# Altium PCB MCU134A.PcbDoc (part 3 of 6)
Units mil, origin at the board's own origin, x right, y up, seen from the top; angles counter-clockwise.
Board outline 4163.98 x 2693.8 mil, 6 copper layers (Top Layer, GND1, SIG1, PWR, GND2, Bottom), stack 58.132 mil thick; 218 components, 287 nets, 1260 pads, 770 vias.
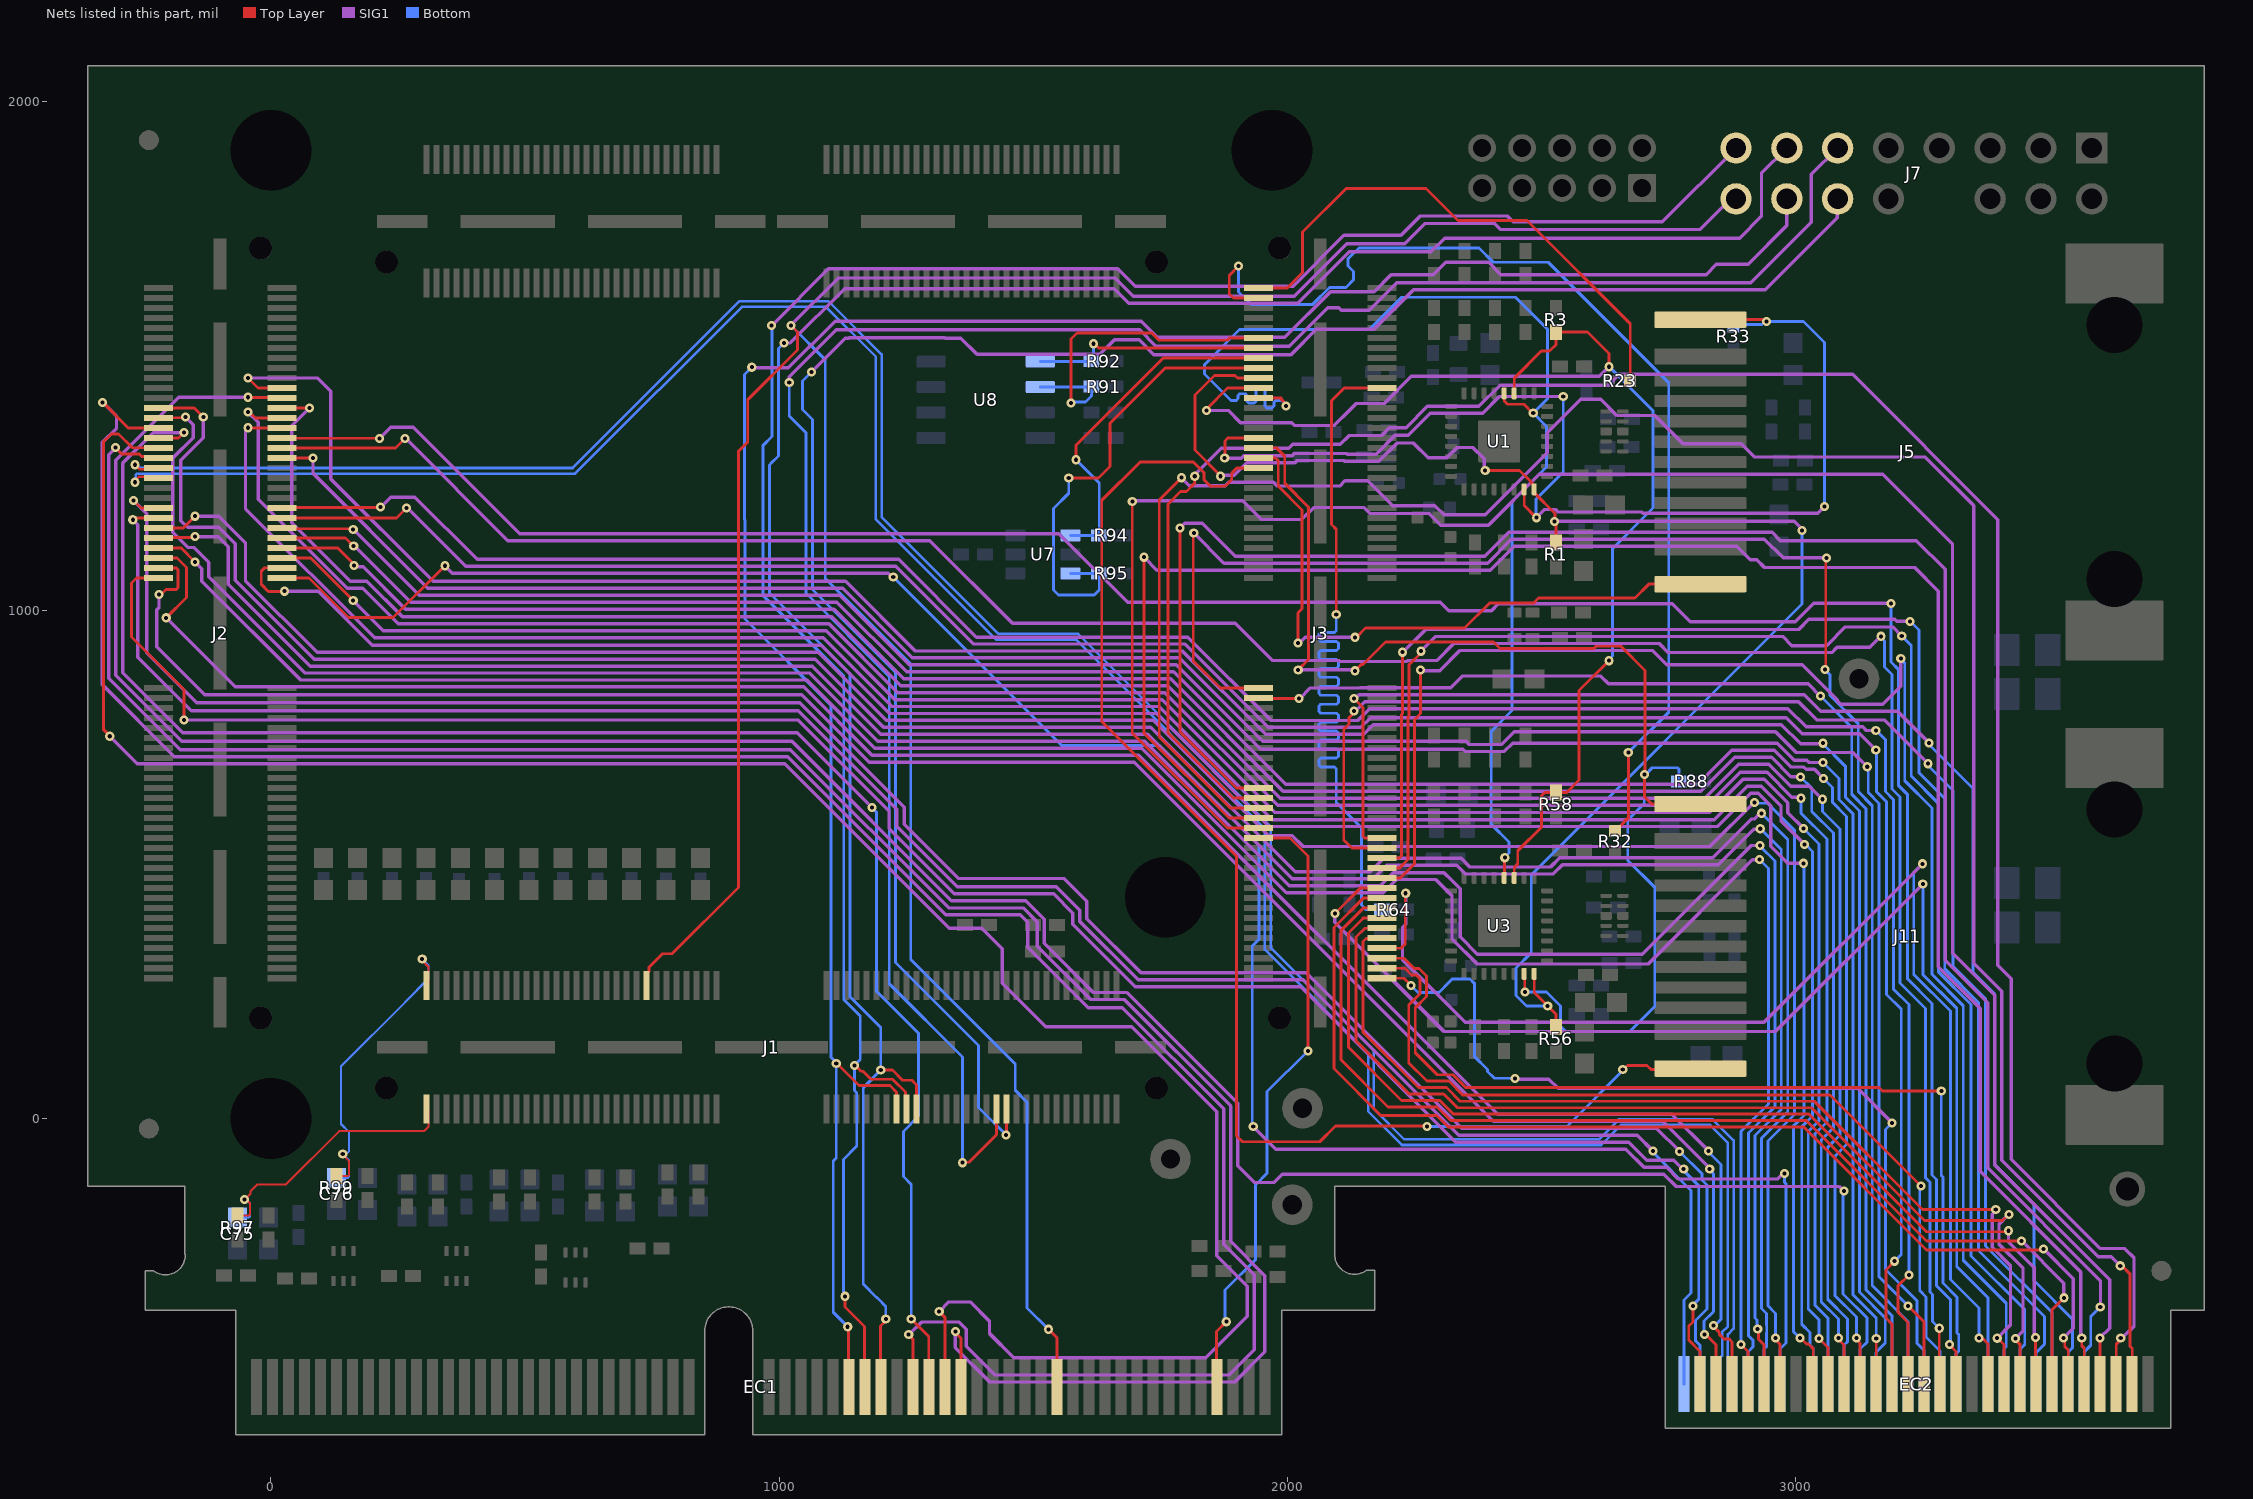
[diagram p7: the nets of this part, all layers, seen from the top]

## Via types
v1: diameter 18, hole 8, Top Layer to Bottom, tented both sides, 761 vias
v2: diameter 19.68, hole 7.87, Top Layer to Bottom, tented both sides, 9 vias

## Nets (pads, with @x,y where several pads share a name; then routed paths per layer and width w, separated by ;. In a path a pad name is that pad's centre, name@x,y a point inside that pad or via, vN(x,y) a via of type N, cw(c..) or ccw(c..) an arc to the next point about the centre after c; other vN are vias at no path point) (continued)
CON1_PIN119: C75.1 J1.119 R97.2 | length 587.5
  Top Layer w4: R97.2@-66.15,-191.38 -43.48,-191.38 -41.14,-189.03 -41.14,-167.11 -48.54,-159.71 v1(-51.64,-159.71) -39.69,-147.77 -39.69,-142.79 -26.91,-130 29.44,-130 134.44,-25 301.25,-25 310.21,-16.04 310.21,-10.38 309.87,-10.04 309.87,14.5 J1.119@305.87,18.5
  Bottom w4: C75.1@-66.15,-195.32 -43.48,-195.31 -41.14,-192.97 -41.14,-170.43 -41.14,-167.11 -48.54,-159.71 v1(-51.64,-159.71)
CON1_PIN120: C76.1 J1.120 R99.2 | length 683.8
  Top Layer w4: R99.2@128.85,-113.07 151.58,-113.07 153.93,-110.73 153.93,-84 141.43,-71.5 v1(141.43,-70) ; v1(297.71,314) 297.71,310.5 310.21,298 310.21,290.38 309.87,290.04 309.87,265.5 J1.120@305.87,261.5
  Bottom w4: C76.1@128.85,-117.01 151.58,-117.01 153.93,-114.66 153.93,-82.5 v1(141.43,-70) 144.1,-67.32 151.2,-67.32 153.93,-64.6 153.93,-26.92 138,-11 138,102.96 264,228.96 264,229.07 310.21,275.28 310.21,301.5 v1(297.71,314)
CON2_PIN21: EC2.146 J2.21 | length 4908.8
  Top Layer w5.66: v1(-45,1457) -25.28,1437.28 J2.21@21.5,1437.28
  SIG1 w6.66: v1(-45,1457) 91.38,1457 117.83,1430.55 117.83,1258.17 319.28,1056.72 1130.72,1056.72 1267.72,919.72 1793.12,919.72 1957.18,755.66 2150.2,755.66 2169.2,774.66 2972.34,774.66 3010,737 3052.67,737 v1(3054,738.33)
  Bottom w5.66: v1(3054,738.33) 3054,737 3098.02,692.98 3098.02,632.5 3125.68,604.84 3125.68,-341.78 3176.66,-392.76 3176.66,-442.19 3158.58,-460.27 EC2.146@3158.58,-522.97
CON2_PIN23: EC2.144 J2.23 | length 5141.8
  Top Layer w5.66: v1(-45,1419) -44.3,1418.3 20.8,1418.3 J2.23@21.5,1417.6
  SIG1 w6.66: v1(-45,1419) -181.25,1419 -304.99,1295.26 -304.99,871.63 -175.36,742 1025.36,742 1339.15,428.22 1485.56,428.22 1521.66,392.11 1521.66,344.66 1618.66,247.66 1684.62,247.66 1902.16,30.11 1902.16,-93.16 1935,-126 1974.22,-126 1990.4,-109.81 2740.81,-109.81 2765,-134 3085.66,-134 3094.66,-143 v1(3095.19,-143)
  Bottom w5.66: v1(3095.19,-143) 3093.66,-144.53 3093.66,-345.56 3141,-392.9 3141,-440.05 3127.09,-453.96 EC2.144@3127.09,-522.97
CON2_PIN25: EC2.142 J2.25 | length 4782.2
  Top Layer w5.66: J2.25@21.5,1397.91 76.05,1397.91 v1(76.25,1398.11)
  SIG1 w6.66: v1(76.25,1398.11) 40.78,1362.64 40.78,1172.22 156,1057 189,1057 258.98,987.02 1103.83,987.02 1239.43,851.42 1764.83,851.42 1985.91,630.34 2821.34,630.34 2888,697 2947.32,697 2990.65,653.67 3027.33,653.67 v1(3053,628)
  Bottom w5.66: v1(3053,628) 3053,604 3087.32,569.68 3087.32,-32.68 3063.32,-56.68 3063.32,-355.78 3102,-394.46 3102,-414 3102.17,-414.17 3102.17,-439.39 3095.59,-445.96 EC2.142@3095.59,-522.97
CON2_PIN26: EC2.132 J2.26 | length 4990.8
  Top Layer w5.66: J2.26@-221.5,1397.91 -150.91,1397.91 v1(-133,1380)
  SIG1 w6.66: v1(-133,1380) -133,1339 -177,1295 -177,1176.08 -163.92,1163 -102.68,1163 -70.22,1130.53 -70.22,1059.22 85.36,903.64 1071.3,903.64 1205.48,769.46 1730.88,769.46 2015.31,485.03 2163.03,485.03 2190,512 2342,512 2359.33,494.67 2517.87,494.67 2536.2,513 2836.7,513 2912.75,589.05 2918.55,589.05 2929.84,600.34 v1(2932.91,600.34)
  Bottom w5.66: v1(2932.91,600.34) 2933.02,600.34 2984.66,548.7 2984.66,12.54 2933.04,-39.08 2933.04,-373.94 2942.75,-383.65 2942.75,-406.05 2943.38,-406.68 2943.38,-421.45 2942.75,-422.08 2942.75,-449.32 2938.11,-453.96 EC2.132@2938.11,-522.97
CON2_PIN27: EC2.140 J2.27 | length 4779.5
  Top Layer w5.66: v1(-45,1390) -42.04,1390 -30.27,1378.23 J2.27@21.5,1378.23
  SIG1 w6.66: v1(-45,1390) -25,1370 -25,1218.68 150.34,1043.34 180.66,1043.34 250.64,973.36 1098.17,973.36 1233.77,837.76 1759.17,837.76 1980.93,616 2826.32,616 2891.32,681 2944,681 2992.83,632.17 3008.83,632.17 v1(3011,630)
  Bottom w5.66: v1(3011,630) 3011,600.63 3062,549.63 3062,-6.9 3038,-30.9 3038,-367 3064.09,-393.09 EC2.140@3064.09,-522.97
CON2_PIN28: EC2.130 J2.28 | length 5053.6
  Top Layer w5.66: J2.28@-221.5,1378.23 -221.03,1378.7 -168.42,1378.7 v1@-167.95,1379.17
  SIG1 w6.66: v1(-167.95,1380) -152.74,1364.8 -152.74,1339.7 -192.95,1299.49 -192.95,1153.03 -163.4,1123.48 -151.55,1123.48 -122,1093.92 -122,1066 67.68,876.32 1059.98,876.32 1194.16,742.14 1719.57,742.14 2003.99,457.71 2183.03,457.71 2208.98,483.66 2308.34,483.66 2324.17,467.83 2340,452 2340,357 2374,323 2698.68,323 2912.68,537 v1(2930,537)
  Bottom w5.66: EC2.130@2906.61,-522.97 2906.61,-459.36 2916,-449.98 2916,-436 2907.72,-427.72 2907.72,-28.59 2959.34,23.03 2959.34,506.25 2930,535.59 v1(2930,537)
CON2_PIN29: EC2.138 J2.29 | length 4729.9
  Top Layer w5.66: v1(-45,1359) -44.77,1358.77 21.27,1358.77 J2.29@21.5,1358.54
  SIG1 w6.66: v1(-45,1359) -45,1355.93 -50,1350.93 -50,1200 203.96,946.04 1086.85,946.04 1222.45,810.44 1747.86,810.44 1970.3,588 2840,588 2905.34,653.34 2933.02,653.34 2971.34,615.02 2971.34,585.66 v1(3018,539)
  Bottom w5.66: v1(3018,539) 3020,539 3033.7,525.3 3033.7,5.04 3012.16,-16.5 3012.16,-405.16 3028.43,-421.43 3028.43,-446.43 3035,-453 3035,-520.57 EC2.138@3032.6,-522.97
CON2_PIN30: EC1.75 J2.30 | length 4669.5
  Top Layer w5.66: v1(-331,1409) -280.54,1358.54 J2.30@-221.5,1358.54 ; v1(1255,-425) 1255,-426.24 1263.25,-434.49 EC1.75@1263.25,-528.32
  SIG1 w6.66: v1(-331,1409) -303.67,1381.67 -303.67,1358.41 -332.31,1329.77 -332.31,854.31 -190,712 1016.73,712 1328.28,400.45 1474.69,400.45 1489,386.14 1489,337 1608,218 1675.64,218 1874.77,18.87 1874.77,-247.66 1935,-307.89 1935,-455 1885,-505 1425,-505 1368.33,-448.33 1368.33,-414.59 1354.41,-400.67 1280.25,-400.67 1255.92,-425 v1(1255,-425)
CON2_PIN31: EC2.155 J2.31 | length 4961
  Top Layer w5.66: J2.31@21.5,1338.86 21.93,1338.43 213.57,1338.43 v1(214,1338) ; v1(3303.33,-445.1) 3303.33,-446.06 3316,-458.73 EC2.155@3316,-532
  SIG1 w6.66: v1(214,1338) 236,1360 280,1360 489.36,1150.64 1550.68,1150.64 1685.98,1015.34 2300.66,1015.34 2317.32,998.68 2401.83,998.68 2415.49,1012.34 2757.67,1012.34 2793,977.01 2999.13,977.01 3035.44,1013.33 v1(3188,1013.33)
  Bottom w5.66: v1(3188,1013.33) 3188,898 3202.32,883.68 3202.32,655.68 3220,638 3220,275 3268.66,226.34 3268.66,-111.62 3277.35,-120.32 3277.35,-329.26 3305.32,-357.22 3305.32,-384.39 3305,-384.71 3305,-443.43 v1(3303.33,-445.1)
CON2_PIN32: EC1.77 J2.32 | length 3407
  Top Layer w5.66: J2.32@-221.5,1338.86 -181.68,1338.86 v1(-171.07,1349.47) ; v1(1260,-395) 1294.39,-429.39 EC1.77@1294.39,-527.97
  SIG1 w6.66: v1(-171.07,1349.47) -231.46,1349.47 -291.33,1289.6 -291.33,877.28 -173.05,759 1035.47,759 v1(1182.94,611.53)
  Bottom w5.66: v1(1182.94,611.53) 1191.34,603.13 1191.34,250.66 1274.49,167.51 1274.49,4.49 1244.51,-25.49 1244.51,-114.51 1260,-130 v1(1260,-395)
CON2_PIN33: EC2.153 J2.33 | length 4891.3
  Top Layer w5.66: J2.33@21.5,1319.17 245.17,1319.17 v1(264,1338) ; v1(3282.89,-412.89) 3282.89,-521.3 EC2.153@3284.57,-522.97
  SIG1 w6.66: v1(264,1338) 265,1338 466.02,1136.98 1296.66,1136.98 1459.28,974.36 1897.64,974.36 1971.02,900.98 2101.85,900.98 2103.77,899.06 2234.59,899.06 2236.51,900.98 2293.98,900.98 2327.44,934.44 2731.69,934.44 2749.44,916.68 3071.34,916.68 3081.66,927 3146.33,927 v1(3168,948.67)
  Bottom w5.66: v1(3168,948.67) 3168,946.18 3175,939.18 3175,888 3189.66,873.34 3189.66,648.28 3205.66,632.28 3205.66,266.34 3256,216 3256,-116.87 3264.69,-125.56 3264.69,-341.29 3269.66,-346.26 3269.66,-399.66 v1(3282.89,-412.89)
CON2_PIN34: EC1.79 J2.34 | length 4521.6
  Top Layer w5.66: v1(-317,752) -317,752.73 -329,764.73 -329,1331.87 -313.87,1347 -299.68,1347 -272.35,1319.67 -221.99,1319.67 J2.34@-221.5,1319.17 ; v1(1315,-380) 1326.1,-391.1 EC1.79@1326.1,-528.18
  SIG1 w6.66: v1(-317,752) -263,698 1011.41,698 1334.88,374.53 1398.72,374.53 1439,334.26 1439,266 1525,180 1694.32,180 1861.11,13.21 1861.11,-270.19 1921.05,-330.12 1921.05,-389.02 1839.17,-470.89 1461.62,-470.89 1413.99,-423.26 1413.99,-398.82 1376.34,-361.17 1333.83,-361.17 v1(1315,-380)
CON2_PIN35: EC2.151 J2.35 | length 4671.8
  Top Layer w5.66: J2.35@21.5,1299.49 v1(82.91,1299.49) v1@83,1299.57 ; v1(3221.58,-369) 3222,-369 3253.07,-400.07 EC2.151@3253.07,-522.97
  SIG1 w6.66: v1(82.91,1299.49) 82.91,1269.09 308.94,1043.06 1125.06,1043.06 1262.06,906.06 1787.46,906.06 1951.52,742 2351.95,742 2358.28,735.67 2421.43,735.67 2446.76,761 2960.59,761 3001.59,720 3113,720 3141,692 v1(3141.17,692)
  Bottom w5.66: v1(3141.17,692) 3143,690.17 3143,641.23 3164.51,619.72 3164.51,-311.51 3221.58,-368.58 v1(3221.58,-369)
CON2_PIN36: EC1.81 J2.36 | length 4454.7
  Top Layer w5.66: v1(-306,1320.17) -292.84,1307.01 -258.79,1307.01 -254.44,1302.66 -224.67,1302.66 J2.36@-221.5,1299.49 ; v1(1346.82,-419) 1346.82,-421.65 1357.66,-432.5 EC1.81@1357.66,-528.25
  SIG1 w6.66: v1(-306,1320.17) -306,1318.61 -318.65,1305.96 -318.65,865.97 -178.34,725.66 1022.39,725.66 1333.94,414.11 1480.35,414.11 1508,386.46 1508,339 1613,234 1678.96,234 1888.43,24.53 1888.43,-242 1955.65,-309.22 1955.65,-459.35 1896.34,-518.66 1414.6,-518.66 1346.82,-450.88 v1(1346.82,-419)
CON2_PIN38: EC2.128 J2.38 | length 4932.2
  Top Layer w5: v1@-266,1286.18 -266,1285.49 -257.54,1277.03 -224.27,1277.03 J2.38@-221.5,1279.8
  Bottom w5: v1(-267.03,1286.18) -263.98,1286.18 -257.6,1279.8 593.86,1279.8 922.28,1608.22 1096.78,1608.22 1201.63,1503.37 1201.63,1183.37 1431.78,953.22 1588.65,953.22 1967.27,574.6 1967.27,336.6 2170.29,133.58 2170.29,18.71 2230.07,-41.07 2613.07,-41.07 2652.35,-1.78 2836.65,-1.78 2878.22,-43.35 2878.22,-413.78 2867,-425 2867,-514.85 EC2.128@2875.12,-522.97
CON2_PIN40: EC2.126 J2.40 | length 4930.3
  Top Layer w5: v1(-267.03,1251.75) -267.03,1254.83 -258.97,1262.89 -224.27,1262.89 J2.40@-221.5,1260.12
  Bottom w5: v1(-267.03,1251.75) v1@-264.97,1253.81 ; v1@-267.03,1255.03 -266.06,1256 -266.06,1265.65 -263.13,1268.58 598.51,1268.58 926.92,1597 1092.13,1597 1190.41,1498.72 1190.41,1178.72 1427.13,942 1584,942 1956.05,569.95 1956.05,331.95 2159.07,128.93 2159.07,14.07 2225.42,-52.29 2617.71,-52.29 2657,-13 2832,-13 2867,-48 2867,-409.13 2855.78,-420.35 2855.78,-466.83 2852.85,-469.76 2852.54,-469.76 2843.62,-478.68 EC2.126@2843.62,-522.97
CON2_PIN45: EC2.149 J2.45 | length 4685.4
  Top Layer w5.66: J2.45@21.5,1201.06 22.46,1202.03 215.03,1202.03 v1(216,1203) ; EC2.149@3221.58,-522.97 3221.58,-401.58 3202,-382 3202,-329 v1(3223,-308)
  SIG1 w6.66: v1(216,1203) 235.59,1222.59 283.41,1222.59 405.68,1100.32 1235.08,1100.32 1388.36,947.04 1804.44,947.04 1968.5,782.98 2138.89,782.98 2162.23,806.32 2984.79,806.32 3020.79,770.32 3132,770.32 3139.01,763.31 3157.69,763.31 v1(3158,763)
  Bottom w5.66: v1(3158,763) 3159,763 3176.83,745.17 3176.83,643.21 3193,627.04 3193,254 3223,224 v1(3223,-308)
CON2_PIN46: EC2.124 J2.46 | length 4320.8
  Top Layer w5.66: v1(-270.24,1215.57) -255.73,1201.06 J2.46@-221.5,1201.06
  SIG1 w6.66: v1(-270.24,1215.57) -244.36,1189.69 -244.36,916.36 -146,818 1041.03,818 1246.57,612.46 1246.57,578.75 1353.32,472 1561,472 1605.34,427.66 1605.34,393.1 1712.12,286.32 2037.36,286.32 2343.02,-19.34 2726.34,-19.34 v1(2772,-65)
  Bottom w5.66: v1(2772,-65) 2816,-109 2816,-121.1 2825.66,-130.76 2825.66,-375.05 2803.17,-397.54 2803.17,-437.4 2812.13,-446.36 EC2.124@2812.13,-522.97
CON2_PIN47: EC2.147 J2.47 | length 4643.9
  Top Layer w5.66: J2.47@21.5,1181.38 247.38,1181.38 v1(267,1201) ; EC2.147@3190.08,-522.97 3190.08,-405.08 3178,-393 3178,-298 v1(3195,-281)
  SIG1 w6.66: v1(267,1201) 269,1201 383.34,1086.66 1229.42,1086.66 1382.7,933.38 1798.78,933.38 1962.84,769.32 2144.54,769.32 2163.88,788.66 2981.34,788.66 3013.34,756.66 3126.34,756.66 v1(3158,725)
  Bottom w5.66: v1(3158,725) 3159,724 3159,643.14 3179,623.14 3179,244 3207.95,215.05 3207.95,-268.05 v1(3195,-281)
CON2_PIN48: EC2.122 J2.48 | length 4238.5
  Top Layer w5.66: v1(-271.67,1178) -268.33,1178 -264.95,1181.38 J2.48@-221.5,1181.38
  SIG1 w6.66: v1(-271.67,1178) -262,1168.33 -262,907.73 -156.27,802 1037.71,802 1231.34,608.37 1231.34,574.66 1350.46,455.54 1545.78,455.54 1591.68,409.64 1591.68,387.44 1706.46,272.66 2031.7,272.66 2337.36,-33 2688.45,-33 v1(2719.61,-64.16)
  Bottom w5.66: v1(2719.61,-64.16) 2719.61,-66.7 2794.65,-141.74 2794.65,-343.39 2780.63,-357.4 EC2.122@2780.63,-522.97
CON2_PIN49: EC2.145 J2.49 | length 4503.8
  Top Layer w5.66: J2.49@21.5,1161.69 22.84,1160.35 160.65,1160.35 v1(162,1159) ; EC2.145@3158.58,-522.97 3158.83,-522.72 v1(3158.83,-433)
  SIG1 w6.66: v1(162,1159) 291.62,1029.4 1119.4,1029.4 1256.4,892.4 1781.81,892.4 1947.88,726.33 2345.67,726.33 2349.99,722.01 2427.09,722.01 2443.21,738.14 2964.14,738.14 2997.26,705.01 3022.23,705.01 3026.9,700.34 v1(3054,700.34)
  Bottom w5.66: v1(3054,700.34) 3085.36,668.98 3085.36,627.26 3113.02,599.6 3113.02,-347.02 3158.83,-392.83 v1(3158.83,-433)
CON2_PIN50: EC2.133 J2.50 | length 4721.8
  Top Layer w5.66: J2.50@-221.5,1161.69 -172.31,1161.69 v1(-149,1185) ; v1(2960.58,-432) 2960.58,-435.34 2969.61,-444.37 EC2.133@2969.61,-522.97
  SIG1 w6.66: v1(-149,1185) -102.21,1185 -50,1132.79 -50,1058.32 91.02,917.3 1076.96,917.3 1211.14,783.12 1736.54,783.12 1963.49,556.17 2009.83,556.17 2031,535 2831.59,535 2917.94,621.35 v1(2919.36,621.35)
  Bottom w5.66: v1(2919.36,621.35) 2920.57,620.13 2944.87,620.13 2998,567 2998,7.98 2945.7,-44.32 2945.7,-368.7 2960.58,-383.58 v1(2960.58,-432)
CON2_PIN51: EC2.143 J2.51 | length 4525.7
  Top Layer w5.66: J2.51@21.5,1142.01 146.99,1142.01 v1(163,1126) ; v1(3120,-432) 3120,-435.34 3127.09,-442.43 EC2.143@3127.09,-522.97
  SIG1 w6.66: v1(163,1126) 165,1126 275.26,1015.74 1113.74,1015.74 1250.74,878.74 1776.15,878.74 1997.23,657.66 2807.66,657.66 2874.48,724.48 2958.48,724.48 2991.6,691.35 3016.57,691.35 3021.24,686.68 3037.32,686.68 v1(3055,669)
  Bottom w5.66: v1(3055,669) 3072.7,651.3 3072.7,622.01 3100.36,594.35 3100.36,-51.64 3077.36,-74.64 3077.36,-348.36 3120,-391 v1(3120,-432)
CON2_PIN52: EC2.131 J2.52 | length 4669
  Top Layer w5.66: J2.52@-221.5,1142.01 -220.17,1143.34 -150.33,1143.34 v1(-149,1144.67) ; v1(2925.55,-414.07) 2927.12,-415.63 2927.12,-434.39 2938.11,-445.38 EC2.131@2938.11,-522.97
  SIG1 w6.66: v1(-149,1144.67) -103.67,1144.67 -83.88,1124.88 -83.88,1050.88 77.02,889.98 1065.64,889.98 1199.82,755.8 1725.22,755.8 2009.65,471.37 2169.37,471.37 2196,498 2333,498 2349.99,481.01 2523.53,481.01 2541.52,499 2848,499 2918.03,569.03 2929.62,569.03 v1(2930.59,570)
  Bottom w5.66: v1(2925.55,-414.07) 2924.51,-413.03 2924.51,-396.58 2920.38,-392.44 2920.38,-33.83 2972,17.79 2972,529 v1@2931,570
CON2_PIN53: EC2.141 J2.53 | length 4482.5
  Top Layer w5.66: J2.53@21.5,1122.32 131.68,1122.32 163.21,1090.79 v1(163.21,1087.71) ; v1(3084.34,-432) 3084.34,-434.68 3095.59,-445.93 EC2.141@3095.59,-522.97
  SIG1 w6.66: v1(163.21,1087.71) 165.38,1085.54 181.46,1085.54 264.92,1002.08 1108.09,1002.08 1245.08,865.08 1770.49,865.08 1991.57,644 2813.32,644 2880.14,710.82 2952.82,710.82 2991.01,672.63 3009.37,672.63 v1(3010,672)
  Bottom w5.66: v1(3010,672) 3032,650 3032,604 3074.66,561.34 3074.66,-18.34 3050.66,-42.34 3050.66,-361.03 3084.34,-394.71 v1(3084.34,-432)
CON2_PIN54: EC2.129 J2.54 | length 4727.9
  Top Layer w5.66: J2.54@-221.5,1122.32 -176.32,1122.32 v1(-149,1095) ; v1(2893,-445) 2906.61,-458.61 EC2.129@2906.61,-522.97
  SIG1 w6.66: v1(-149,1095) -149,1094.82 -135.66,1081.48 -135.66,1056.66 58.34,862.66 1054.32,862.66 1188.5,728.48 1713.91,728.48 1998.34,444.05 2188.69,444.05 2214.64,470 2292.58,470 2324,438.58 2324,353.68 2373.83,303.85 2709.85,303.85 2915.26,509.26 v1(2929,509.26)
  Bottom w5.66: v1(2893,-445) 2893,-25.4 2946.68,28.28 2946.68,491.51 2929,509.19 v1(2929,509.26)
CON2_PIN55: EC2.139 J2.55 | length 4411.1
  Top Layer w5.66: J2.55@21.5,1102.64 78.36,1102.64 v1(162,1019) ; v1(3046.26,-433) 3064.09,-450.83 EC2.139@3064.09,-522.97
  SIG1 w6.66: v1(162,1019) 221.3,959.7 1092.51,959.7 1228.11,824.1 1753.52,824.1 1975.62,602 2831.64,602 2896.64,667 2938.68,667 2985,620.68 2985,601.41 v1(3015.71,570.71)
  Bottom w5.66: v1(3015.71,570.71) 3046.36,540.05 3046.36,-4.64 3025,-26 3025,-375 3046.26,-396.26 v1(3046.26,-433)
CON2_PIN56: EC2.127 J2.56 | length 4146
  Top Layer w5.66: J2.56@-221.5,1102.64 -184.46,1102.64 -165.91,1084.09 -165.91,1025.09 v1(-206,985) ; v1(2838.68,-407.32) 2838.68,-409.56 2849.92,-420.81 2849.92,-424.74 2859.49,-434.3 2869.45,-434.3 2875.12,-439.97 EC2.127@2875.12,-522.97
  SIG1 w6.66: v1(-206,985) -70,849 1048.67,849 1182.85,714.82 1707.18,714.82 2414.02,7.98 2756.81,7.98 v1(2828.93,-64.16)
  Bottom w5.66: v1(2828.93,-64.16) 2828.93,-65.93 2853.45,-90.45 2853.45,-395.12 2841.25,-407.32 v1(2838.68,-407.32)
CON2_PIN57: EC2.137 J2.57 | length 4487.3
  Top Layer w5: EC2.137@3032.6,-522.97 EC2.137@3032.6,-520.57
  Top Layer w5.66: J2.57@23.69,1083.48 23.63,1083.42 -12.22,1083.42 -19,1076.64 -19,1051 -5,1037 26.28,1037 v1(26.65,1037.36) ; v1(3008.64,-432.36) 3010.13,-432.36 3021.76,-443.98 3025.76,-443.98 3035,-453.22 EC2.137@3035,-520.57
  SIG1 w6.66: v1(26.65,1037.36) 93.32,1037.36 199.72,930.96 1082.61,930.96 1216.79,796.78 1742.2,796.78 1964.64,574.34 2846.42,574.34 2911.76,639.68 2926.95,639.68 2951.24,615.39 2951.24,535.76 2985,502 v1(3015.87,502)
  Bottom w5.66: v1(3008.64,-432.36) 2996.36,-420.08 2996.36,-14.39 3016.53,5.78 3016.53,501.34 v1(3015.87,502)
CON2_PIN58: EC2.125 J2.58 | length 4149.2
  Top Layer w5.66: J2.58@-221.5,1082.95 -186.27,1082.95 -182.95,1079.64 -182.95,1044.32 -186.27,1041 -206.66,1041 -216.78,1030.88 v1(-220.12,1030.88) ; v1(2821,-425) 2823.24,-425 2843.53,-445.28 2843.53,-522.87 EC2.125@2843.62,-522.97
  SIG1 w6.66: v1(-220.12,1030.88) -220.12,1004.71 -224.33,1000.5 -224.33,928.33 -130,834 1044.35,834 1177.19,701.16 1698.84,701.16 2405.68,-5.68 2738.6,-5.68 2831.14,-98.22 v1(2831.14,-99.58)
  Bottom w5.66: v1(2821,-425) 2820.17,-424.17 2820.17,-398.44 2838.32,-380.29 2838.32,-109.07 2831.14,-101.89 v1(2831.14,-99.58)
CON2_PIN59: EC2.134 J2.59 | length 4298.9
  Top Layer w5.66: J2.59@21.5,1063.27 74.97,1063.27 152.79,985.45 240.45,985.45 v1(342.5,1087.5)
  SIG1 w6.66: v1(342.5,1087.5) 357,1073 1215.01,1073 1222.43,1065.58 v1(1224.58,1065.58) ; v1(1933,-16) 1977.32,-60.32 2666,-60.32 2701.83,-96.15 2746.47,-96.15 2769.65,-119.33 2964.39,-119.33 2975.46,-108.26 v1(2978.53,-108.26)
  Bottom w5.66: v1(1224.58,1065.58) 1556.16,734 1748,734 1944.5,537.5 1944.5,352.5 1931,339 1931,-14 v1(1933,-16) ; EC2.134@2969.61,-522.97 2969.61,-453.96 2981.36,-442.21 2981.36,-128.58 2978.53,-125.75 v1(2978.53,-108.26)
CON2_PIN60: EC2.123 J2.60 | length 4171.3
  Top Layer w5.66: J2.60@-221.5,1063.27 -264.35,1063.27 -274.02,1053.6 -274.02,947.02 -171,844 v1(-171,784) ; v1(2798.46,-369) 2798,-369.46 2798,-400.79 2790.02,-408.77 2790.02,-436.29 2812.13,-458.39 EC2.123@2812.13,-522.97
  SIG1 w6.66: v1(-171,784) 1036.39,784 1216.34,604.06 1216.34,570.34 1344.8,441.88 1540.12,441.88 1578.02,403.98 1578.02,381.78 1700.8,259 2026.05,259 2331.71,-46.66 2671.66,-46.66 2707.49,-82.49 2760.61,-82.49 2777.79,-99.67 v1(2779.97,-99.67)
  Bottom w5.66: v1(2779.97,-99.67) 2779.97,-102.97 2809.49,-132.49 2809.49,-355.76 2798.46,-366.79 v1(2798.46,-369)
CON3_PIN2: EC2.152 J3.2 | length 1780.6
  Top Layer w5.66: J3.2@2186.5,275.87 2229.38,275.87 v1(2243.51,261.74)
  SIG1 w6.66: v1(2448,78.83) 2449.43,77.4 2514.39,77.4 2532.79,59 3122.12,59 v1(3190.12,-9)
  Bottom w5.66: v1(2243.51,261.74) 2257.25,248 2298.22,248 2317,266.78 2317,267 2324.55,274.55 2359.45,274.55 2368,266 2368,122.37 2394.17,96.2 2394.17,92.61 2407.82,78.97 v1@2447.86,78.97 ; v1(3190.12,-9) 3177.17,-21.95 3177.17,-297.17 3239.41,-359.41 3239.41,-442.65 3253.07,-456.31 EC2.152@3253.07,-522.97
CON3_PIN4: EC2.154 J3.4 | length 1774.2
  Top Layer w5.66: J3.4@2186.5,295.55 2231.33,295.55 2244.54,282.34 2253.66,282.34 2261.34,274.66 2261.34,245.34 2239,223 2239,109 2274.66,73.34 2318.2,73.34 2345.2,46.34 3067.58,46.34 v1(3246.86,-132.95)
  Bottom w5.66: v1(3246.86,-132.95) 3244.5,-135.31 3244.5,-142.27 3244.34,-142.43 3244.34,-338.85 3257,-351.51 3257,-429.99 3284.57,-457.55 EC2.154@3284.57,-522.97
CON3_PIN6: EC2.156 J3.6 | length 1930.7
  Top Layer w5.66: J3.6@2186.5,315.24 2229.55,315.24 2249.79,295 2258.91,295 2274,279.9 2274,240.1 2251.66,217.76 2251.66,129.34 2295,86 2326.08,86 2351.08,61 3164.06,61 3171.06,54 v1(3286.83,54)
  Bottom w5.66: v1(3286.83,54) 3286.83,-111.89 3290.01,-115.07 3290.01,-324.01 3317.98,-351.98 3317.98,-421.98 3321.13,-425.13 3321.13,-444.06 ; EC2.156@3316,-532 3316,-462.99 3321.16,-457.83 3321.16,-444.09
CON3_PIN8: EC2.159 J3.8 | length 2581.5
  Top Layer w5.66: J3.8@2186.5,334.92 2223.92,334.92 2232,343 2232,442 v1(2233,443) ; v1(3361.15,-432) 3363.51,-434.36 3369.49,-434.36 3379.06,-443.92 EC2.159@3379.06,-522.97
  SIG1 w6.66: v1(2233,443) 2233,381.83 2226.67,375.5 2226.67,312.41 2350.08,189 2938,189 v1(3250,501)
  Bottom w5.66: v1(3250,501) 3232.66,483.66 3232.66,283.34 3304.66,211.34 3304.66,-316.85 3361.15,-373.34 v1(3361.15,-432)
CON3_PIN10: EC2.161 J3.10 | length 1986.1
  Top Layer w5.66: J3.10@2186.5,354.61 2185.89,354 2155,354 2149.12,348.12 2149.12,169.5 2257.94,60.68 2312.96,60.68 2339.96,33.68 3036.88,33.68 3249.56,-179 v1(3394,-179) ; v1(3396.81,-432.45) 3397.62,-432.45 3410,-444.83 EC2.161@3410,-522.42
  SIG1 w6.66: v1(3394,-179) 3394,-181.31 3386.73,-188.57 3386.73,-253.3 3423,-289.56 3423,-406.26 v1(3396.81,-432.45)
CON3_PIN12: EC2.163 J3.12 | length 2070.3
  Top Layer w5.66: J3.12@2186.5,374.29 2152.72,374.29 2135.34,356.91 2135.34,152.66 2239.98,48.02 2307.72,48.02 2334.72,21.02 3031.64,21.02 3253.66,-201 3407.27,-201 3419.27,-189 v1(3420,-189) ; v1(3433,-433) 3433,-436.34 3442.05,-445.39 EC2.163@3442.05,-522.97
  SIG1 w6.66: v1(3420,-189) 3400.39,-208.61 3400.39,-247.64 3447.73,-294.98 3447.73,-418.27 v1(3433,-433)
CON3_PIN14: EC2.165 J3.14 | length 2077.9
  Top Layer w5.66: J3.14@2186.5,393.98 2149.46,393.98 2145.86,390.37 2120.11,364.62 2120.11,139.89 2224.64,35.36 2300.02,35.36 2327.02,8.36 3026.4,8.36 3257.76,-223 3417,-223 v1(3419,-221) ; v1(3472.1,-431.01) 3472.1,-521.53 EC2.165@3473.54,-522.97
  SIG1 w6.66: v1(3419,-221) 3419,-242.82 3469.96,-293.78 3469.96,-428.86 v1(3472.1,-431.01)
CON3_PIN16: EC2.167 J3.16 | length 2166
  Top Layer w5.66: J3.16@2186.5,413.66 2149.46,413.66 2106,370.2 2106,115 2198.3,22.7 2294.78,22.7 2321.78,-4.3 3021.15,-4.3 3257.85,-241 v1(3445,-241) ; EC2.167@3505.04,-522.97 3505.04,-375.96 v1(3528,-353)
  SIG1 w6.66: v1(3445,-241) 3528,-324 v1(3528,-353)
CON3_PIN18: EC2.169 J3.18 | length 2242.4
  Top Layer w5.66: J3.18@2186.5,433.35 2149.46,433.35 2092,375.88 2092,98 2184,6 2293.58,6 2316.78,-17.2 3016.15,-17.2 3257.78,-258.83 3486.17,-258.83 v1(3488,-257) ; v1(3527.51,-432) 3529.87,-434.36 3529.87,-448.87 3536.54,-455.54 EC2.169@3536.54,-522.97
  SIG1 w6.66: v1(3488,-257) 3546.33,-315.33 3546.33,-413.18 v1(3527.51,-432)
CON3_PIN20: EC2.160 J3.20 | length 2534.1
  Top Layer w5.66: v1(2093.6,403) 2143.63,453.03 J3.20@2186.5,453.03
  SIG1 w6.66: v1(2093.6,403) 2093.6,385.73 2308.32,171 2960.49,171 v1(3250.49,461)
  Bottom w5.66: v1(3250.49,461) 3250.49,283.41 3317.32,216.58 3317.32,-291.32 3378.98,-352.98 3378.98,-439.83 3379.06,-439.91 EC2.160@3379.06,-522.97
CON3_PIN22: EC2.162 J3.22 | length 3055.1
  Top Layer w5.66: J3.22@2186.5,472.72 2221.81,472.72 2250.2,501.1 2250.2,784.43 2262.27,796.51 v1(2262.27,882.65)
  SIG1 w6.66: v1(2262.27,882.65) 2264.19,880.73 2299.73,880.73 2339.78,920.78 2718.24,920.78 2746.39,892.62 3013.3,892.62 3081.9,824.02 3081.9,822 3089.23,814.67 3171.76,814.67 3207.17,850.08 v1(3207.17,905)
  Bottom w5.66: v1(3207.17,905) 3207.17,903.32 3214.98,895.51 3214.98,664.24 3268.32,610.9 3268.32,283.49 3330,221.81 3330,-279 3414.64,-363.64 3414.64,-448.77 3410,-453.41 3410,-522.42 EC2.162@3410.55,-522.97
CON3_PIN24: EC2.164 J3.24 | length 3042.5
  Top Layer w5.66: J3.24@2186.5,492.4 2220.4,492.4 2237.54,509.54 2237.54,789.68 2239.54,791.68 2239.54,892.54 2263,916 v1(2263,919.31)
  SIG1 w6.66: v1(2263,919.31) 2292.03,948.34 2974.66,948.34 2992.66,930.34 3061.02,930.34 3097.68,967 3191,967 v1(3209,949)
  Bottom w5.66: v1(3209,949) 3227.64,930.36 3227.64,673.58 3280.98,620.24 3280.98,288.73 3345.44,224.27 3345.44,-270.44 3451,-376 3451,-445.01 3442.05,-453.96 EC2.164@3442.05,-522.97
CON3_PIN26: EC2.166 J3.26 | length 3086.3
  Top Layer w5.66: J3.26@2186.5,512.09 2186.62,512.21 2220.21,512.21 2224.88,516.88 2224.88,794.92 2226.88,796.92 2226.88,917.27 v1(2227,917.39)
  SIG1 w6.66: v1(2227,917.39) 2227.39,917.39 2272,962 3006,962 3026,982 3195.32,982 3199.32,978 v1(3225,978)
  Bottom w5.66: v1(3225,978) 3226.01,978 3243,961.01 3243,679.98 3293.64,629.34 3293.64,294.51 3359.84,228.32 3359.84,-259.84 3489.93,-389.93 3489.93,-444.24 3473.54,-460.63 EC2.166@3473.54,-522.97
CON3_PIN28: EC2.168 J3.28 | length 2853.9
  Top Layer w5.66: v1(2131.29,801.31) 2131.29,797.97 2121.59,788.27 2121.59,776.3 2111,765.71 2111,548 2127.23,531.77 J3.28@2186.5,531.77
  SIG1 w6.66: v1(2131.29,801.31) 2133.61,801.31 2152.28,819.98 3005.91,819.98 3041.89,784 3174.83,784 v1(3260.83,698)
  Bottom w5.66: v1(3260.83,698) 3260.83,694.68 3310,645.51 3310,300 3374,236 3374,-251 3505.04,-382.04 EC2.168@3505.04,-522.97
CON3_PIN29: EC1.113 J3.29 | length 1233.4
  Top Layer w5.66: EC1.113@1860.86,-529.14 1860.86,-419.14 v1(1880,-400) ; J3.29@1943.5,551.46 2005.14,551.46 2040.42,516.18 v1(2040.42,132.95)
  Bottom w5.66: v1(1880,-400) 1877.64,-397.64 1877.64,-390.77 1877.38,-390.51 1877.38,-337.83 1937.17,-278.05 1937.17,-130.84 1960.17,-107.84 1960.17,52.7 v1(2040.42,132.95)
CON3_PIN30: EC2.170 J3.30 | length 2874.8
  Top Layer w5.66: v1(2130.95,826.31) 2131.51,826.31 2149.12,808.7 2149.12,554.77 2152.44,551.46 J3.30@2186.5,551.46
  SIG1 w6.66: v1(2130.95,826.31) 2134.02,826.31 2141.05,833.34 2146.45,833.34 2146.75,833.64 3017.36,833.64 3049.99,801.01 3200.66,801.01 v1(3262.67,739)
  Bottom w5.66: v1(3262.67,739) 3262.67,735.66 3349,649.33 3349,288 3392,245 3392,-91.34 3469,-168.34 3469,-319.22 3545.34,-395.56 3545.34,-450.66 3536.54,-459.46 EC2.170@3536.54,-522.97
CON3_PIN31: EC2.173 J3.31 | length 4322.3
  Top Layer w5.66: v1(1695,1214) 1695,758.52 1882.38,571.14 J3.31@1943.5,571.14 ; v1(3599,-432) 3599,-522.44 EC2.173@3599.53,-522.97
  SIG1 w6.66: v1(1695,1214) 1695.98,1214.98 1912.37,1214.98 1948.82,1178.53 2028.53,1178.53 2052,1202 2151,1202 2162.78,1190.22 2279.15,1190.22 2301.9,1167.47 2395.88,1167.47 2495.58,1267.16 3171.85,1267.16 3309,1130.02 3309,325 3392,242 3392,-91.68 3618,-317.68 3618,-413 v1(3599,-432)
CON3_PIN33: EC2.171 J3.33 | length 3949.7
  Top Layer w5.66: v1(1718,1104.26) 1718,757.83 1885,590.83 J3.33@1943.5,590.83 ; v1(3563.17,-432) 3563.17,-447.46 3568.03,-452.32 EC2.171@3568.03,-522.97
  SIG1 w6.66: v1@1718.26,1104.26 1743.54,1078.98 2399.66,1078.98 2446.68,1125.99 2884.32,1125.99 2911.32,1099 2924,1099 2939,1084 3234.32,1084 3281,1037.32 3281,298.53 3363.23,216.3 3363.23,-103.86 3561.57,-302.2 3561.57,-430.4 v1(3563.17,-432)
CON3_PIN35: EC2.177 J3.35 | length 4464.2
  Top Layer w5.66: v1@1791.6,1260.46 1748.14,1217.01 1748.14,750.26 1887.89,610.51 J3.35@1943.5,610.51 ; v1(3639,-290) 3642.34,-290 3657.83,-305.49 3657.83,-448.09 3662.52,-452.78 EC2.177@3662.52,-522.97
  SIG1 w6.66: v1@1791.65,1260.65 1807.09,1245.2 1877.97,1245.2 1884.41,1251.64 1972.87,1251.64 1980.19,1244.32 2102.99,1244.32 2113.45,1254.78 2158.71,1254.78 2207.85,1205.64 2290.36,1205.64 2308.54,1187.46 2389.46,1187.46 2511.45,1309.45 2511.45,1349.37 2577.41,1415.33 2616.43,1415.33 2648.65,1383.11 2722.82,1383.11 2778.62,1327.31 2893.61,1327.31 2919.59,1301.33 3255.67,1301.33 3351,1206 3351,305.62 3406,250.62 3406,-82 3596,-272 3621,-272 v1(3639,-290)
  other v1: 1791.6,1260.69
CON3_PIN37: EC2.175 J3.37 | length 4404.4
  Top Layer w5.66: v1(1817.93,1263.53) 1817.93,1249.85 1801.52,1233.44 1790.16,1233.44 1765.17,1208.45 1765.17,758.87 1893.85,630.2 J3.37@1943.5,630.2 ; EC2.175@3631.02,-522.97 3631.02,-444.32 3640,-435.34 v1(3640,-432)
  SIG1 w6.66: v1(1817.93,1263.53) 1817.93,1266.23 1870.33,1318.62 2003,1318.62 2010.71,1326.34 2104.34,1326.34 2121.77,1343.77 2185.4,1343.77 2200.63,1359 2233.68,1359 2275.72,1401.04 2377.04,1401.04 2419,1443 2632,1443 2653,1464 3112.32,1464 3398,1178.32 3398,301 3424.44,274.56 3424.44,-80.44 3600.03,-256.03 3647.86,-256.03 3666,-274.17 3666,-409.07 3643.07,-432 v1(3640,-432)
CON3_PIN39: EC2.172 J3.39 | length 3930.4
  Top Layer w5.66: v1(1789,1162) 1789,760.96 1900.08,649.88 J3.39@1943.5,649.88
  SIG1 w6.66: v1(1789,1162) 1789.57,1162 1798.57,1171 1833,1171 1897.7,1106.3 2388.35,1106.3 2435.36,1153.31 2953.93,1153.31 2970.25,1137 3237.92,1137 3294.66,1080.26 3294.66,311.34 3378,228 3378,-97 3600,-319 3600,-370.67 v1(3599.67,-371)
  Bottom w5.66: EC2.172@3568.03,-522.97 3568.03,-459.33 3581,-446.36 3581,-390 3599.67,-371.33 v1(3599.67,-371)
CON3_PIN57: EC2.148 J3.57 | length 2553.1
  Top Layer w5.66: J3.57@1943.5,827.05 1944.03,826.52 2022.48,826.52 v1(2023,826)
  SIG1 w6.66: v1(2023,826) 2024.56,826 2045.56,847 2142.71,847 2143.01,847.3 2321.3,847.3 2344.46,870.46 2616.54,870.46 2632,855 3025,855 v1(3049,831)
  Bottom w5.66: v1(3049,831) 3110.68,769.32 3110.68,637.74 3138.34,610.08 3138.34,-336.53 3190.08,-388.27 EC2.148@3190.08,-522.97
CON3_PIN59: EC2.150 J3.59 | length 3402.2
  Top Layer w5.66: v1(1816,1152) 1815,1151 1815,900 1868.27,846.73 J3.59@1943.5,846.73 ; v1(3058,883) 3059.5,884.5 3059.5,1101.5 v1(3061,1103)
  SIG1 w6.66: v1(1816,1152) 1875.36,1092.64 2394,1092.64 2441.02,1139.65 2938.82,1139.65 2975.47,1103 v1(3061,1103)
  Bottom w5.66: v1(3058,883) 3068,873 3068,832 3123.34,776.66 3123.34,642.99 3151,615.33 3151,-329 3221.58,-399.58 EC2.150@3221.58,-522.97
DAC_SPI_CLK: EC1.71 J1.41 J7.13 | length 4529.4
  Top Layer w5.66: EC1.71@1199.85,-528.73 1199.85,-408.49 1210,-398.34 v1(1210,-395) ; v1(1200,95) 1223.28,95 1243.08,75.2 1261.23,75.2 1270.43,66 J1.41@1270.43,18.5
  SIG1 w6.66: v1(1009.66,1525.83) 1022.3,1525.83 1129.25,1632.78 1659.46,1632.78 1688.24,1604 2020.46,1604 2121.63,1705.18 2282.67,1705.18 2309.7,1732.21 2890.21,1732.21 2933,1775 2933,1859.44 J7.13@2982.94,1909.38
  Bottom w5.66: v1(1009.66,1525.83) 998.66,1514.82 998.66,1303.66 984.31,1289.31 984.31,1288.6 981.33,1285.61 981.33,1033.63 1139.77,875.18 1139.77,239.32 1200,179.1 v1(1200,95) 1165.5,60.5 1165.5,-325.72 1191.95,-352.17 1192.39,-352.17 1202.39,-362.17 1202.39,-362.6 1209.98,-370.2 v1(1210,-395)
DAC_SPI_PICO: EC1.67 J1.45 J7.14 | length 4530.5
  Top Layer w5.66: v1(1112.41,108) 1114,108 1157.49,64.51 1217.96,64.51 1231.06,51.41 J1.45@1231.06,18.5 ; v1(1135,-410) 1136.86,-411.86 EC1.67@1136.86,-528.73
  SIG1 w6.66: v1(946.33,1478.13) 947.7,1476.76 1018.39,1476.76 1110.42,1568.78 1712.63,1568.78 1744.54,1536.87 1995.19,1536.87 2084.98,1626.66 2170.66,1626.66 2204.05,1660.05 2287.33,1660.05 2311.92,1684.64 2395.95,1684.64 2420.28,1660.31 2824.01,1660.31 2844.38,1680.67 2906.67,1680.67 2982.94,1756.94 J7.14@2982.94,1809.38
  Bottom w5.66: v1(946.33,1478.13) 932.17,1463.97 932.17,1178.17 933,1177.34 933,982.63 1101.79,813.84 1101.79,120.53 v1@1114.32,108 ; v1(1112.41,108) 1112.41,-77.81 1106.5,-83.72 1106.5,-381.5 v1(1135,-410)
DAC_SPI_POCI: EC1.69 J1.43 J7.15 | length 4447.9
  Top Layer w5.66: v1(1130,-350) 1130,-371.15 1168.35,-409.51 EC1.69@1168.35,-528.73 ; v1(1148.07,104.45) 1149.54,104.45 1161.17,92.82 1165.18,92.82 1180.83,77.17 1223.2,77.17 1248.69,51.68 1248.69,20.56 J1.43@1250.75,18.5
  SIG1 w6.66: v1(985.13,1560.03) 1097.14,1672.05 1666.39,1672.05 1701.04,1637.39 2011.35,1637.39 2111.52,1737.56 2223.71,1737.56 2261.8,1775.65 2433.14,1775.65 2444.78,1764 2737.56,1764 J7.15@2882.94,1909.38
  Bottom w5.66: v1(985.13,1560.03) 986,1559.17 986,1342 968.67,1324.67 968.67,1028.39 1127.11,869.94 1127.11,234.08 1159.78,201.41 1159.78,116.17 v1(1148.07,104.45) 1148.07,54.8 1152.84,50.03 1152.84,-54.34 1126.47,-80.71 1126.47,-340.51 1127.64,-341.68 1127.64,-347.64 v1(1130,-350)
DAC_SPI_PTE: EC1.93 J1.76 J7.16 | length 5746.3
  Top Layer w5.66: J1.76@738.94,261.5 738.94,284.04 743.79,288.89 743.79,297.41 770.38,324 789.56,324 920,454.44 920,1312.68 938.3,1330.98 938.3,1414.12 1036,1511.81 1036,1547.52 v1(1023.14,1560.38) ; v1(1530,-415) 1546.72,-431.72 EC1.93@1546.72,-528.32
  SIG1 w6.66: v1(1023.14,1560.38) 1116.32,1653.56 1661.48,1653.56 1697.04,1618 2013.35,1618 2116.52,1721.17 2230.88,1721.17 2270.53,1760.83 2408.08,1760.83 2419.91,1749 2812,1749 2872.38,1809.38 J7.16@2882.94,1809.38
  Bottom w5.66: v1(1023.14,1560.38) 1090.88,1492.64 1090.88,1062.49 1258.98,894.4 1258.98,312.74 1464.57,107.15 1464.57,55.43 1488.08,31.92 1488.08,-373.08 v1(1530,-415)
ECAT_PHY0_CLK: J3.117 R32.1 | length 2151.2
  Top Layer w5.66: v1(1904,1677) 1885.83,1658.83 1885.83,1622.45 1893.82,1614.45 J3.117@1943.5,1614.45 ; R32.1@2645,565.67 2653.98,574.65 2671,591.67 v1(2671,719.81)
  Bottom w5.66: v1(1904,1677) 1904,1626.35 1928.47,1601.88 2050.1,1601.88 2083.22,1635 2115.22,1635 2130.34,1650.11 2130.34,1666.55 2119.67,1677.21 2119.67,1691.55 2141.05,1712.92 2377.08,1712.92 2405.36,1684.64 2513.36,1684.64 2750.53,1447.47 2750.53,799.34 v1(2671,719.81)
ECAT_PHY1_CLK: J3.119 R23.1 | length 1081.9
  Top Layer w5.66: J3.119@1943.5,1634.13 2000.06,1634.13 2030.17,1664.25 2030.17,1744.09 2116.01,1829.92 2272.94,1829.92 2336.04,1766.82 2471.6,1766.82 2674.73,1563.69 R23.1@2674.73,1451.12
EEPROM_I2CSCL: J1.23 J7.12 | length 3958.2
  Top Layer w5.66: v1(1446.74,-32.43) 1447.59,-31.58 J1.23@1447.6,18.5
  SIG1 w6.66: v1(1064,1469) 1130.38,1535.38 1137.37,1535.38 1137.71,1535.72 1326.05,1535.72 1326.39,1535.38 1357.35,1535.38 1389.42,1503.31 1631.31,1503.31 1660,1532 1708.39,1532 1737.45,1502.94 2007.29,1502.94 2056.93,1552.59 2170.59,1552.59 2248.34,1630.34 2940.34,1630.34 3082.38,1772.38 3082.38,1808.82 J7.12@3082.94,1809.38
  Bottom w5.66: v1(1064,1469) 1046.17,1451.17 1046.17,1394.83 1065.56,1375.44 1065.56,1040.86 1229.32,877.1 1229.32,306.59 1392.54,143.37 1392.54,21.77 1445.56,-31.25 v1(1446.74,-32.43)
EEPROM_I2CSDA: J1.25 J7.11 | length 4163.2
  Top Layer w5.66: v1(1360.92,-87.14) 1361.69,-86.37 1373.57,-86.37 1427.91,-32.03 J1.25@1427.91,18.5
  SIG1 w6.66: v1(1020.03,1447.73) 1020.03,1459.08 1112.6,1551.65 1709.49,1551.65 1741.47,1519.67 2004.06,1519.67 2079.47,1595.07 2101.34,1595.07 2106.42,1590 2161,1590 2215,1644 2912,1644 3031,1763 3031,1857.44 J7.11@3082.94,1909.38
  Bottom w5.66: v1(1020.03,1447.73) 1020,1382 1052.9,1349.1 1052.9,1033.67 1216.66,869.91 1216.66,265.14 1360.92,120.88 v1(1360.92,-87.14)
ESC_I2C_SCL: J3.109 R91.1 U8.6 | length 674
  Top Layer w5.66: v1(1574.43,1407.86) 1574.43,1533.84 1586.15,1545.56 1733.35,1545.56 1747.79,1531.12 1882.05,1531.12 1886.63,1535.71 J3.109@1943.5,1535.71
  Bottom w5.66: U8.6@1513.88,1439.03 1613.97,1439.03 R91.1@1614.97,1440.03 1614.97,1421.57 1603.07,1409.67 1576.24,1409.67 v1(1574.43,1407.86)
ESC_I2C_SDA: J3.107 R92.1 U8.5 | length 465.4
  Top Layer w5.66: v1(1618.73,1524.27) 1620.52,1524.27 1628.93,1515.85 J3.107@1943.33,1515.85
  Bottom w5.66: U8.5@1513.88,1489.03 1613.97,1489.03 1618.73,1493.79 v1(1618.73,1524.27)
ESC_LED_ERR: J3.105 R94.1 U7.1 | length 683.8
  Top Layer w5.66: v1(1584.05,1296.01) 1584.05,1324.44 1755.95,1496.34 J3.105@1943.5,1496.34
  Bottom w5.66: U7.1@1573.07,1147.21 R94.1@1629.96,1147.21 1629.96,1250.11 v1(1584.05,1296.01)
ESC_LED_LINK0_ACTIVE: J3.83 J11.12 | length 2736.1
  Top Layer w5.66: J3.83@1943.16,1280.14 1901.29,1280.14 1890.58,1269.43 1890.58,1257.1 1877.25,1243.78 1848.99,1243.78 1835.76,1257 1835.76,1270.98 1814.89,1291.86 1710.63,1291.86 1635,1216.23 1635,780.94 1900,515.94 1900,-34.34 1911.68,-46.02 2063.98,-46.02 2094.86,-15.14 2274.27,-15.14 v1(2274.96,-15.84) ; v1(2660,96) 2661.22,96 2669.49,104.27 2707.73,104.27 2716,96 2810.89,96 J11.12@2812.8,97.91
  Bottom w5.66: v1(2274.96,-15.84) 2550.16,-15.84 2660,94 v1(2660,96)
ESC_LED_LINK1_ACTIVE: J3.85 J5.12 | length 1261.9
  Top Layer w5.66: J3.85@1943.5,1299.49 1976.69,1299.49 1982.2,1293.98 1982.2,1244.43 2029.2,1197.43 2029.2,1002.91 2021.08,994.8 v1(2021.08,935.72) ; v1(2133,946.67) 2136.01,946.67 2154,964.66 2348.47,964.66 2397.65,1013.84 2484.37,1013.84 2494.58,1024.06 2684.06,1024.06 2711.19,1051.19 J5.12@2812.8,1051.19
  SIG1 w6.66: v1(2021.08,935.72) 2024.15,935.72 2035.43,947 2132.67,947 v1(2133,946.67)
ESC_LED_RUN: J3.103 R95.1 U7.3 | length 933.1
  Top Layer w5.66: v1(1570,1260) 1628.34,1260 1651.14,1282.8 1651.14,1367.99 1759.8,1476.65 J3.103@1943.5,1476.65
  Bottom w5.66: v1(1570,1260) 1570,1230 1540,1200 1540,1040 1550,1030 1620,1030 1629.96,1039.96 R95.1@1629.96,1072.4 U7.3@1573.07,1072.4
ESC_MDIO_CLK: J3.97 U1.12 U3.12 | length 2367.7
  Top Layer w5.66: J3.97@1943.61,1417.49 1988.02,1417.49 1988.02,1414.94 1997.5,1405.46 v1(1997.5,1402.12) ; U3.12@2426.8,473.53 2427.4,474.13 2427.4,512.4 v1(2428,513) ; U1.12@2426.8,1426.81 2426.94,1426.67 2426.94,1411.37 2433.14,1405.17 2465.59,1405.17 2482.74,1388.01 v1(2483.91,1388.01)
  Bottom w5.66: v1(1997.5,1402.12) 1997.5,1404.46 1989.21,1412.75 1980,1412.75 1977.17,1412.75 1973.64,1409.22 1973.64,1401.67 1970.11,1398.14 1959.51,1398.14 1955.98,1401.67 1955.98,1433.94 1952.45,1437.48 1941.85,1437.48 1938.32,1433.94 1938.32,1411.19 1934.79,1407.66 1924.19,1407.66 1920.66,1411.19 1920.66,1422.29 1917.13,1425.82 1906.53,1425.82 1903,1422.29 1903,1416.28 1899.47,1412.75 1897.46,1412.75 1897.39,1412.83 1889.29,1412.83 1837.09,1465.03 1837.09,1483.11 1906.06,1552.09 2161.25,1552.09 2225.05,1615.89 2448.98,1615.89 2512.35,1552.52 2512.35,1416.45 v1(2483.91,1388.01) 2510.32,1361.61 2510.32,1281.9 2442.34,1213.92 2442.34,802.34 2401.22,761.22 2401.22,578.83 2436,544.06 2436,522.49 2428,514.49 v1(2428,513)
ESC_MDIO_DATA: J3.99 R3.1 R58.2 U1.11 U3.11 | length 2467.3
  Top Layer w5.66: v1(1840.85,1393.01) 1840.85,1395.51 1882.44,1437.11 J3.99@1943.33,1437.11 ; U3.11@2446.49,473.53 2446.49,494 2453.51,501.03 2453.51,526.51 2500,573 2500,635 2506.6,641.6 R58.2@2528.47,641.6 2549.94,641.6 2574,665.66 2574,841.8 v1(2632.87,900.67) ; U1.11@2446.49,1426.81 2446.49,1456.5 2499.82,1509.83 2516.15,1509.83 2528.47,1522.15 R3.1@2528.47,1547.63 2590.46,1547.63 2633,1505.1 v1(2633,1479)
  SIG1 w6.66: v1(1840.85,1393.01) 1883.83,1393.01 1907.89,1368.94 2008.66,1368.94 2014.1,1363.5 2092.4,1363.5 2123.33,1394.43 2135.59,1406.7 2190.93,1406.7 2244.23,1460 2614,1460 v1(2633,1479)
  Bottom w5.66: v1(2632.87,900.67) 2632.87,903.19 2639.83,910.16 2639.83,1120.83 2719.84,1200.84 2719.84,1392.56 2633.4,1479 v1(2633,1479)
ESC_PHY0_LINKSTATUS: J3.87 J11.1 R88.2 U3.31 | length 2563.2
  Top Layer w5.66: J3.87@1943.5,1319.17 1943.92,1319.59 1978.23,1319.59 1994.86,1302.96 1994.86,1249.67 2041.86,1202.68 2041.86,902.86 2021.65,882.65 v1(2021.46,882.65) ; v1(2133,880.73) 2145.5,893.23 2149.23,893.23 2193.14,937.14 2405.86,937.14 2418.64,924.36 2602.86,924.36 2607.5,929 2656.5,929 2704,881.5 2704,678 v1(2703,677) 2703,632.8 2717.08,618.72 2812.47,618.72 J11.1@2812.8,618.38 ; U3.31@2466.17,284.55 2467.1,283.62 2467.1,249.95 v1(2468.03,249.02)
  SIG1 w6.66: v1(2021.46,882.65) 2021.65,882.46 2131.27,882.46 v1(2133,880.73)
  Bottom w5.66: v1(2468.03,249.02) 2509.87,249.02 2537.4,221.49 2537.4,181.6 2547.66,171.34 2674.34,171.34 2723,220 2723,454.7 2670,507.7 2670,587.15 2702.44,619.59 2702.44,676.44 v1(2703,677) 2705.15,677 2718.22,690.07 2767.76,690.07 2771.07,686.75 R88.2@2771.07,663.27
ESC_PHY1_LINKSTATUS: J3.89 J5.1 R33.2 U1.31 | length 2383.1
  Top Layer w5.66: v1(1876.82,1299.19) 1877.34,1299.72 1877.34,1333.09 1882.87,1338.62 1900.21,1338.62 1900.45,1338.86 J3.89@1943.5,1338.86 ; U1.31@2466.17,1237.83 2466.17,1205.83 v1(2490,1182) ; J5.1@2812.8,1571.66 2939.34,1571.66 v1(2943,1568)
  SIG1 w6.66: v1(1876.82,1299.19) 1909.19,1299.19 1913.9,1303.9 2009.57,1303.9 2013.97,1308.3 2116.53,1308.3 2118.15,1306.67 2174.58,1306.67 2211.91,1344 2238,1344 2281.38,1387.38 2384.36,1387.38 2417.56,1420.57 v1(2543.02,1420.57) ; v1(2490,1182) 2506.23,1198.23 2527.74,1198.23 2532.81,1193.16 2697.15,1193.16 2699.89,1190.42 3043.42,1190.42 v1(3057,1204)
  Bottom w5.66: v1(2490,1182) 2489.31,1182.69 2489.31,1218.46 2543.02,1272.17 v1(2543.02,1420.57) ; R33.2@2877.52,1562.41 2934.07,1562.41 2939.66,1568 v1(2943,1568) 3015.55,1568 3057,1526.55 v1(3057,1204)
ESC_PHY_RESETn: J3.101 R1.1 R56.1 U1.32 U3.32 | length 3000.3
  Top Layer w5.66: v1(1868.83,1263.53) 1868.83,1264.44 1818.17,1315.1 1818.17,1423.39 1856.88,1462.11 1896.57,1462.11 1901.7,1456.97 J3.101@1943.5,1456.97 ; v1(2389.41,1274.98) 2457.09,1274.98 2479.92,1252.15 2479.92,1250.65 2485.91,1244.67 U1.32@2485.86,1237.83 ; U3.32@2485.86,284.55 2485.86,247.82 v1(2512.34,221.33) 2528.34,205.33 R56.1@2528.34,179.97 ; U1.32@2485.86,1237.83 2485.86,1230.94 2526.56,1190.24 2526.56,1175.73 v1(2525.66,1174.83) ; R1.1@2528.34,1133.25 v1@2528.34,1174.66
  SIG1 w6.66: v1(1868.83,1263.53) 1870.6,1265.3 1895.3,1265.3 1920.24,1290.24 2015.23,1290.24 2019.63,1294.64 2110.87,1294.64 2112.5,1293.01 2180.24,1293.01 2216.23,1329 2248,1329 2277,1300 2314,1300 2334.12,1320.12 2364.88,1320.12 2387.24,1297.76 2387.24,1277.15 v1(2389.41,1274.98) ; v1(2525.66,1174.83) 2525.82,1174.99 2997.4,1174.99 3013,1159.39 v1(3013,1157)
  Bottom w5.66: v1(2512.34,221.33) 2470.5,221.33 2450.2,241.64 2450.2,296.2 2480,326 2480,479.22 3013,1012.22 v1(3013,1157)
ESC_RX0_CLK: J3.100 R64.1 | length 1704.7
  Top Layer w5.66: v1(2096.28,991.33) 2096.25,991.37 2096.25,1159.13 2086.85,1168.53 2086.85,1412.24 2111.9,1437.28 J3.100@2186.5,1437.28
  Bottom w5.66: v1(2096.28,991.33) 2096.37,991.25 2096.37,969.86 2096.37,959.79 2092.83,956.26 2065.97,956.26 2062.44,952.73 2062.44,942.13 2065.97,938.6 2096.93,938.6 2100.46,935.07 2100.46,924.47 2096.93,920.94 2065.97,920.94 2062.44,917.41 2062.44,906.81 2065.97,903.28 2096.93,903.28 2100.46,899.75 2100.46,889.15 2096.93,885.62 2065.97,885.62 2062.44,882.09 2062.44,871.49 2065.97,867.96 2096.93,867.96 2100.46,864.43 2100.46,853.83 2096.93,850.3 2065.97,850.3 2062.44,846.77 2062.44,836.17 2065.97,832.64 2096.93,832.64 2100.46,829.11 2100.46,818.51 2096.93,814.98 2065.97,814.98 2062.44,811.45 2062.44,800.85 2065.97,797.32 2096.93,797.32 2100.46,793.79 2100.46,783.19 2096.93,779.66 2065.97,779.66 2062.44,776.13 2062.44,765.53 2065.97,762 2096.93,762 2100.46,758.47 2100.46,747.87 2096.93,744.34 2065.97,744.34 2062.44,740.81 2062.44,730.21 2065.97,726.68 2096.93,726.68 2100.46,723.15 2100.46,712.55 2096.93,709.02 2065.97,709.02 2062.44,705.49 2062.44,694.89 2065.97,691.36 2092.83,691.36 2096.37,687.83 2096.37,685 2096.37,680.81 2096.34,621.66 2146,572 2146,419.65 2154.97,410.68 R64.1@2185.9,410.68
